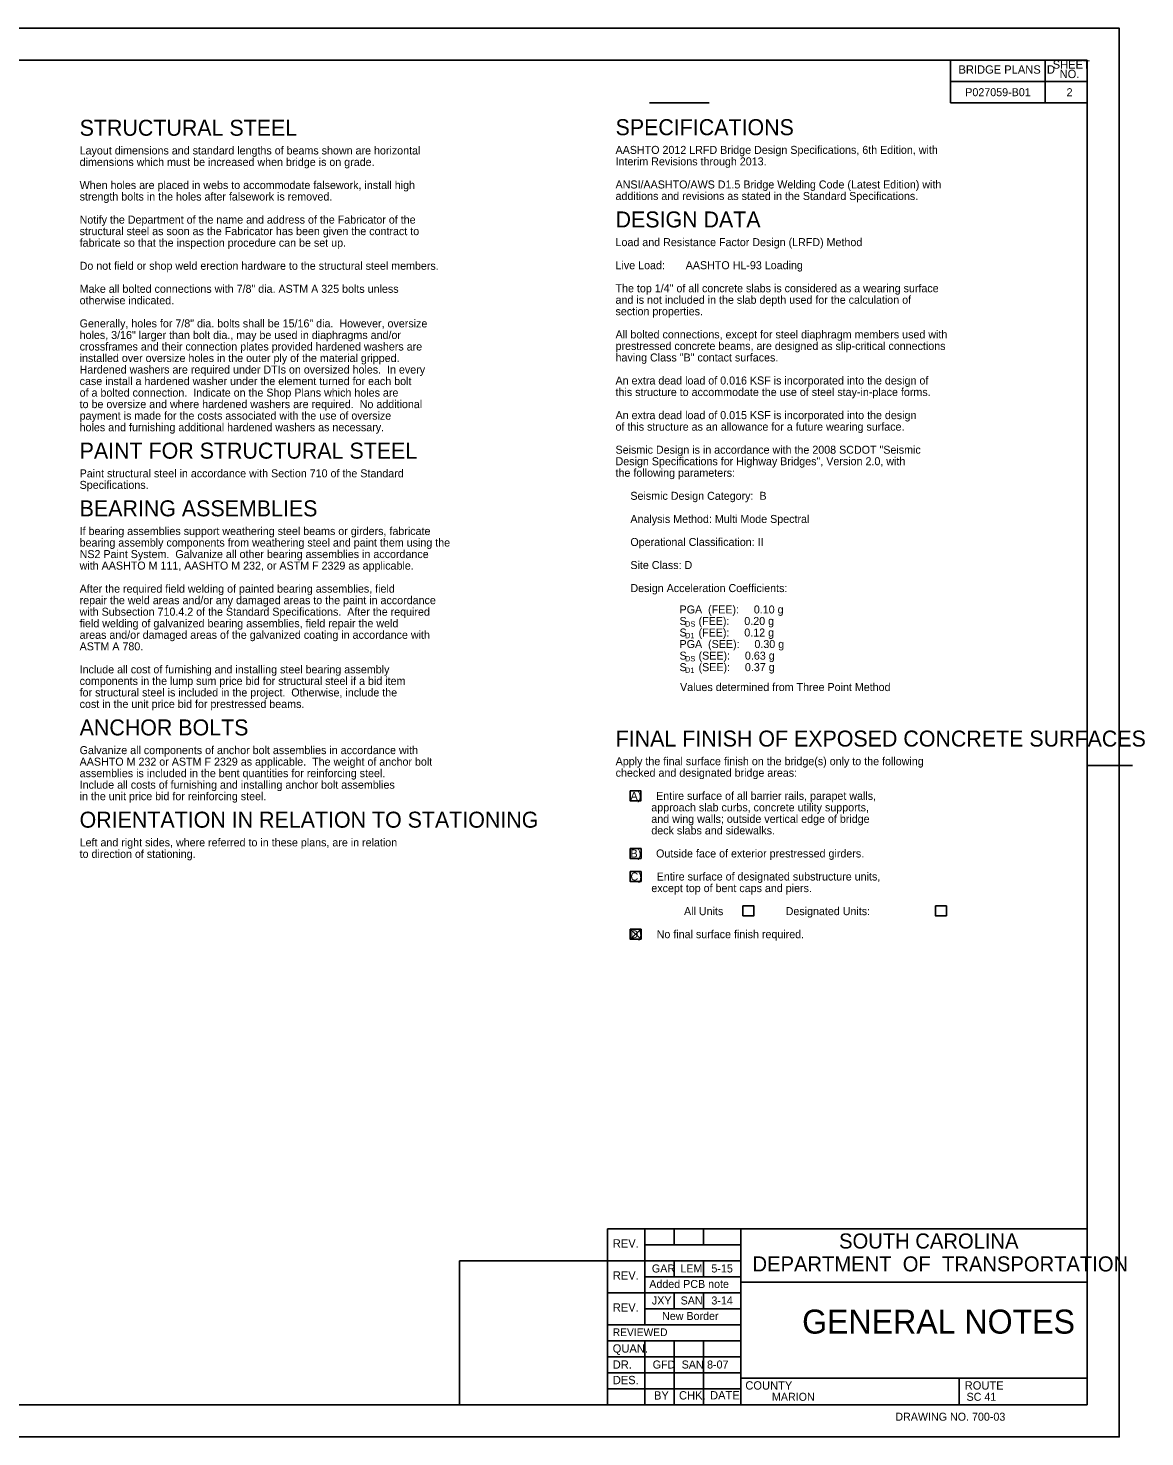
# Model space of a CAD drawing. Extents: x -1.3 to 94.5, y -4.9 to 22.8.
# Drawn here: x 17.63 to 35.08, y 0.82 to 22.82 of the extents above; entities that cross this region are included whole.
import ezdxf

# ---------------------------------------------------------------- set-up
doc = ezdxf.new("R2010")
doc.units = 0
for name, color, linetype in [('BR_AUTO DIMENSION', 7, 'Continuous'), ('BR_BORDER LINES', 7, 'Continuous'), ('BR_TEXT', 7, 'Continuous'), ('RD_SHT_IplotShp', 7, 'Continuous')]:
    doc.layers.add(name, color=color, linetype=linetype)

msp = doc.modelspace()

# ---------------------------------------------------------------- linework, layer by layer
at = {"layer": 'BR_AUTO DIMENSION'}
for p, q in [((27.032, 8.745), (27.203, 8.591)), ((27.203, 8.745), (27.032, 8.591))]:
    msp.add_line(p, q, dxfattribs=at)
at = {"layer": 'BR_BORDER LINES'}
for p, q in [((-1.323, 22.82), (34.677, 22.82)), ((34.177, 22.318), (0.511, 22.318)), ((32.037, 21.651), (32.037, 22.318)), ((33.343, 22.318), (33.343, 22.318)), ((33.517, 21.651), (33.517, 22.318)), ((33.759, 22.318), (33.759, 22.318)), ((34.177, 1.318), (34.177, 22.318)), ((32.037, 21.989), (34.177, 21.989)), ((28.266, 21.651), (27.337, 21.651)), ((34.177, 21.651), (32.037, 21.651)), ((34.177, 21.154), (34.177, 21.651)), ((34.177, 14.105), (34.177, 21.154)), ((34.177, 11.304), (34.882, 11.304)), ((26.677, 1.318), (26.677, 4.068)), ((26.677, 4.068), (34.177, 4.068)), ((27.261, 4.068), (27.261, 2.568)), ((27.719, 3.818), (27.719, 4.068)), ((28.177, 3.818), (28.177, 4.068)), ((28.761, 1.318), (28.761, 4.068)), ((27.261, 3.818), (28.761, 3.818)), ((24.365, 3.568), (26.677, 3.568)), ((24.365, 1.318), (24.365, 3.568)), ((26.677, 3.568), (28.761, 3.568)), ((27.719, 3.318), (27.719, 3.568)), ((28.177, 3.318), (28.177, 3.568)), ((27.261, 3.318), (28.761, 3.318)), ((28.761, 3.235), (34.177, 3.235)), ((28.761, 3.235), (28.761, 3.235)), ((34.177, 3.235), (34.177, 3.235)), ((26.677, 3.068), (28.761, 3.068)), ((27.719, 2.818), (27.719, 3.068)), ((28.177, 2.818), (28.177, 3.068)), ((27.261, 2.818), (28.761, 2.818)), ((26.677, 2.568), (28.761, 2.568)), ((26.677, 2.318), (28.761, 2.318)), ((27.261, 2.318), (27.261, 1.318)), ((27.719, 2.318), (27.719, 1.318)), ((28.177, 2.318), (28.177, 1.318)), ((26.677, 2.068), (28.761, 2.068)), ((26.677, 1.818), (28.761, 1.818)), ((26.677, 1.568), (28.761, 1.568)), ((28.761, 1.735), (34.177, 1.735)), ((32.177, 1.318), (32.177, 1.735)), ((0.511, 1.318), (34.177, 1.318)), ((-1.323, 0.82), (34.677, 0.82))]:
    msp.add_line(p, q, dxfattribs=at)
at = {"layer": 'BR_TEXT'}
for points in [[(27.031, 10.907), (27.202, 10.907), (27.202, 10.753), (27.031, 10.753)], [(27.031, 10.907), (27.202, 10.907), (27.202, 10.753), (27.031, 10.753)], [(27.032, 10.007), (27.203, 10.007), (27.203, 9.853), (27.032, 9.853)], [(27.032, 9.647), (27.203, 9.647), (27.203, 9.492), (27.032, 9.492)], [(28.796, 9.111), (28.967, 9.111), (28.967, 8.957), (28.796, 8.957)], [(31.804, 9.111), (31.975, 9.111), (31.975, 8.957), (31.804, 8.957)], [(27.032, 8.745), (27.203, 8.745), (27.203, 8.591), (27.032, 8.591)]]:
    msp.add_lwpolyline(points, close=True, dxfattribs=at)
at = {"layer": 'RD_SHT_IplotShp'}
msp.add_lwpolyline([(-1.323, 22.818), (34.677, 22.818), (34.677, 0.818), (-1.323, 0.818)], close=True, dxfattribs=at)

# ---------------------------------------------------------------- texts
at = {"layer": 'BR_TEXT'}
for s, height, p in [('BRIDGE PLANS ID', 0.13, (32.164, 22.109)), ('SHEET', 0.13, (33.636, 22.187)), ('NO.', 0.13, (33.744, 22.04)), ('P027059-B01', 0.125, (32.27, 21.757)), ('2', 0.125, (33.853, 21.757)), ('STRUCTURAL STEEL', 0.25, (18.431, 21.139)), ('SPECIFICATIONS', 0.25, (26.805, 21.148)), ('Layout dimensions and standard lengths of beams shown are horizontal ', 0.125, (18.431, 20.847)), ('AASHTO 2012 LRFD Bridge Design Specifications, 6th Edition, with', 0.125, (26.805, 20.856)), ('dimensions which must be increased when bridge is on grade.', 0.125, (18.431, 20.667)), ('Interim Revisions through 2013. ', 0.125, (26.805, 20.676)), ('When holes are placed in webs to accommodate falsework, install high', 0.125, (18.431, 20.307)), ('strength bolts in the holes after falsework is removed.', 0.125, (18.431, 20.127)), ('ANSI/AASHTO/AWS D1.5 Bridge Welding Code (Latest Edition) with', 0.125, (26.805, 20.316)), ('additions and revisions as stated in the Standard Specifications.', 0.125, (26.805, 20.136)), ('Notify the Department of the name and address of the Fabricator of the ', 0.125, (18.431, 19.767)), ('DESIGN DATA', 0.25, (26.805, 19.707)), ('structural steel as soon as the Fabricator has been given the contract to ', 0.125, (18.431, 19.587)), ('fabricate so that the inspection procedure can be set up.', 0.125, (18.431, 19.406)), ('Load and Resistance Factor Design (LRFD) Method', 0.125, (26.805, 19.415)), ('Do not field or shop weld erection hardware to the structural steel members. ', 0.125, (18.431, 19.046)), ('Live Load:       AASHTO HL-93 Loading ', 0.125, (26.805, 19.055)), ('Make all bolted connections with 7/8" dia. ASTM A 325 bolts unless', 0.125, (18.431, 18.686)), ('The top 1/4" of all concrete slabs is considered as a wearing surface ', 0.125, (26.805, 18.695)), ('otherwise indicated.', 0.125, (18.431, 18.506)), ('and is not included in the slab depth used for the calculation of ', 0.125, (26.805, 18.515)), ('Generally, holes for 7/8" dia. bolts shall be 15/16" dia.  However, oversize', 0.125, (18.431, 18.146)), ('section properties.', 0.125, (26.805, 18.335)), ('holes, 3/16" larger than bolt dia., may be used in diaphragms and/or ', 0.125, (18.431, 17.965)), ('All bolted connections, except for steel diaphragm members used with', 0.125, (26.805, 17.974)), ('crossframes and their connection plates provided hardened washers are', 0.125, (18.431, 17.785)), ('prestressed concrete beams, are designed as slip-critical connections', 0.125, (26.805, 17.794)), ('installed over oversize holes in the outer ply of the material gripped.', 0.125, (18.431, 17.605)), ('having Class "B" contact surfaces.', 0.125, (26.805, 17.614)), ('Hardened washers are required under DTIs on oversized holes.  In every ', 0.125, (18.431, 17.425)), ('An extra dead load of 0.016 KSF is incorporated into the design of ', 0.125, (26.805, 17.254)), ('case install a hardened washer under the element turned for each bolt ', 0.125, (18.431, 17.245)), ('of a bolted connection.  Indicate on the Shop Plans which holes are ', 0.125, (18.431, 17.065)), ('this structure to accommodate the use of steel stay-in-place forms.', 0.125, (26.805, 17.074)), ('to be oversize and where hardened washers are required.  No additional', 0.125, (18.431, 16.885)), ('payment is made for the costs associated with the use of oversize ', 0.125, (18.431, 16.705)), ('An extra dead load of 0.015 KSF is incorporated into the design', 0.125, (26.805, 16.713)), ('holes and furnishing additional hardened washers as necessary.', 0.125, (18.431, 16.524)), ('of this structure as an allowance for a future wearing surface.', 0.125, (26.805, 16.533)), ('PAINT FOR STRUCTURAL STEEL', 0.25, (18.431, 16.096)), ('Seismic Design is in accordance with the 2008 SCDOT "Seismic', 0.125, (26.805, 16.173)), ('Design Specifications for Highway Bridges", Version 2.0, with', 0.125, (26.805, 15.993)), ('Paint structural steel in accordance with Section 710 of the Standard ', 0.125, (18.431, 15.804)), ('the following parameters:', 0.125, (26.805, 15.813)), ('Specifications.', 0.125, (18.431, 15.624)), ('BEARING ASSEMBLIES', 0.25, (18.431, 15.195)), ('     Seismic Design Category:  B', 0.125, (26.805, 15.453)), ('     Analysis Method: Multi Mode Spectral', 0.125, (26.805, 15.092)), ('If bearing assemblies support weathering steel beams or girders, fabricate ', 0.125, (18.431, 14.903)), ('bearing assembly components from weathering steel and paint them using the ', 0.125, (18.431, 14.723)), ('     Operational Classification: II', 0.125, (26.805, 14.732)), ('NS2 Paint System.  Galvanize all other bearing assemblies in accordance ', 0.125, (18.431, 14.543)), ('with AASHTO M 111, AASHTO M 232, or ASTM F 2329 as applicable. ', 0.125, (18.431, 14.363)), ('     Site Class: D', 0.125, (26.805, 14.372)), ('After the required field welding of painted bearing assemblies, field ', 0.125, (18.431, 14.003)), ('     Design Acceleration Coefficients:', 0.125, (26.805, 14.012)), ('repair the weld areas and/or any damaged areas to the paint in accordance ', 0.125, (18.431, 13.823)), ('with Subsection 710.4.2 of the Standard Specifications.  After the required ', 0.125, (18.431, 13.643)), ('PGA  (FEE):     0.10 g', 0.125, (27.805, 13.678)), ('field welding of galvanized bearing assemblies, field repair the weld ', 0.125, (18.431, 13.462)), ('S    (FEE):     0.20 g', 0.125, (27.805, 13.498)), ('S    (FEE):     0.12 g', 0.125, (27.805, 13.318)), ('DS', 0.0833, (27.892, 13.472)), ('ASTM A 780.', 0.125, (18.431, 13.102)), ('areas and/or damaged areas of the galvanized coating in accordance with ', 0.125, (18.431, 13.282)), ('PGA  (SEE):     0.30 g', 0.125, (27.805, 13.138)), ('D1', 0.0833, (27.892, 13.291)), ('S    (SEE):     0.63 g', 0.125, (27.805, 12.957)), ('DS', 0.0833, (27.892, 12.93)), ('Include all cost of furnishing and installing steel bearing assembly ', 0.125, (18.431, 12.742)), ('S    (SEE):     0.37 g', 0.125, (27.805, 12.777)), ('D1', 0.0833, (27.892, 12.75)), ('components in the lump sum price bid for structural steel if a bid item ', 0.125, (18.431, 12.562)), ('Values determined from Three Point Method', 0.125, (27.813, 12.466)), ('for structural steel is included in the project.  Otherwise, include the ', 0.125, (18.431, 12.382)), ('cost in the unit price bid for prestressed beams.', 0.125, (18.431, 12.202)), ('ANCHOR BOLTS', 0.25, (18.431, 11.773)), ('FINAL FINISH OF EXPOSED CONCRETE SURFACES', 0.25, (26.807, 11.599)), ('Galvanize all components of anchor bolt assemblies in accordance with ', 0.125, (18.431, 11.481)), ('AASHTO M 232 or ASTM F 2329 as applicable.  The weight of anchor bolt ', 0.125, (18.431, 11.301)), ('assemblies is included in the bent quantities for reinforcing steel.  ', 0.125, (18.431, 11.121)), ('Apply the final surface finish on the bridge(s) only to the following ', 0.125, (26.807, 11.308)), ('checked and designated bridge areas:', 0.125, (26.807, 11.128)), ('Include all costs of furnishing and installing anchor bolt assemblies ', 0.125, (18.431, 10.941)), ('in the unit price bid for reinforcing steel.', 0.125, (18.431, 10.761)), ('     A)     Entire surface of all barrier rails, parapet walls, ', 0.125, (26.807, 10.767)), ('ORIENTATION IN RELATION TO STATIONING', 0.25, (18.43, 10.332)), ('            approach slab curbs, concrete utility supports,', 0.125, (26.807, 10.587)), ('            and wing walls; outside vertical edge of bridge', 0.125, (26.807, 10.407)), ('            deck slabs and sidewalks.', 0.125, (26.807, 10.227)), ('Left and right sides, where referred to in these plans, are in relation ', 0.125, (18.431, 10.04)), ('to direction of stationing.', 0.125, (18.431, 9.86)), ('     B)     Outside face of exterior prestressed girders.', 0.125, (26.807, 9.867)), ('     C)     Entire surface of designated substructure units,', 0.125, (26.807, 9.507)), ('            except top of bent caps and piers.', 0.125, (26.807, 9.326)), ('                       All Units                     Designated Units:', 0.125, (26.807, 8.966)), ('     D)     No final surface finish required.  ', 0.125, (26.807, 8.606)), ('SOUTH CAROLINA', 0.23585, (30.298, 3.759)), ('REV.', 0.13, (26.762, 3.774)), ('DEPARTMENT  OF  TRANSPORTATION', 0.23585, (28.945, 3.401)), ('REV.', 0.13, (26.762, 3.274)), ('GAR', 0.125, (27.373, 3.385)), ('LEM', 0.125, (27.818, 3.385)), ('5-15', 0.125, (28.303, 3.385)), ('Added PCB note', 0.125, (27.332, 3.143)), ('REV.', 0.13, (26.762, 2.774)), ('JXY', 0.125, (27.373, 2.885)), ('SAN', 0.125, (27.822, 2.885)), ('3-14', 0.125, (28.303, 2.885)), ('New Border', 0.125, (27.532, 2.643)), ('GENERAL NOTES', 0.375, (29.721, 2.43)), ('REVIEWED', 0.12, (26.761, 2.392)), ('QUAN.', 0.13, (26.761, 2.133)), ('DR.', 0.13, (26.761, 1.882)), ('GFD', 0.125, (27.385, 1.885)), ('SAN', 0.125, (27.838, 1.885)), ('8-07 ', 0.125, (28.235, 1.885)), ('DES.', 0.13, (26.762, 1.64)), ('COUNTY', 0.13, (28.833, 1.556)), ('ROUTE', 0.13, (32.261, 1.556)), ('BY', 0.13, (27.406, 1.4)), ('CHK.', 0.13, (27.797, 1.401)), ('DATE', 0.13, (28.282, 1.402)), ('MARION', 0.125, (29.249, 1.381)), ('SC 41', 0.125, (32.29, 1.381)), ('DRAWING NO. 700-03', 0.125, (31.177, 1.07))]:
    msp.add_text(s, height=height, dxfattribs=at).set_placement(p)

doc.saveas('drawing.dxf')
